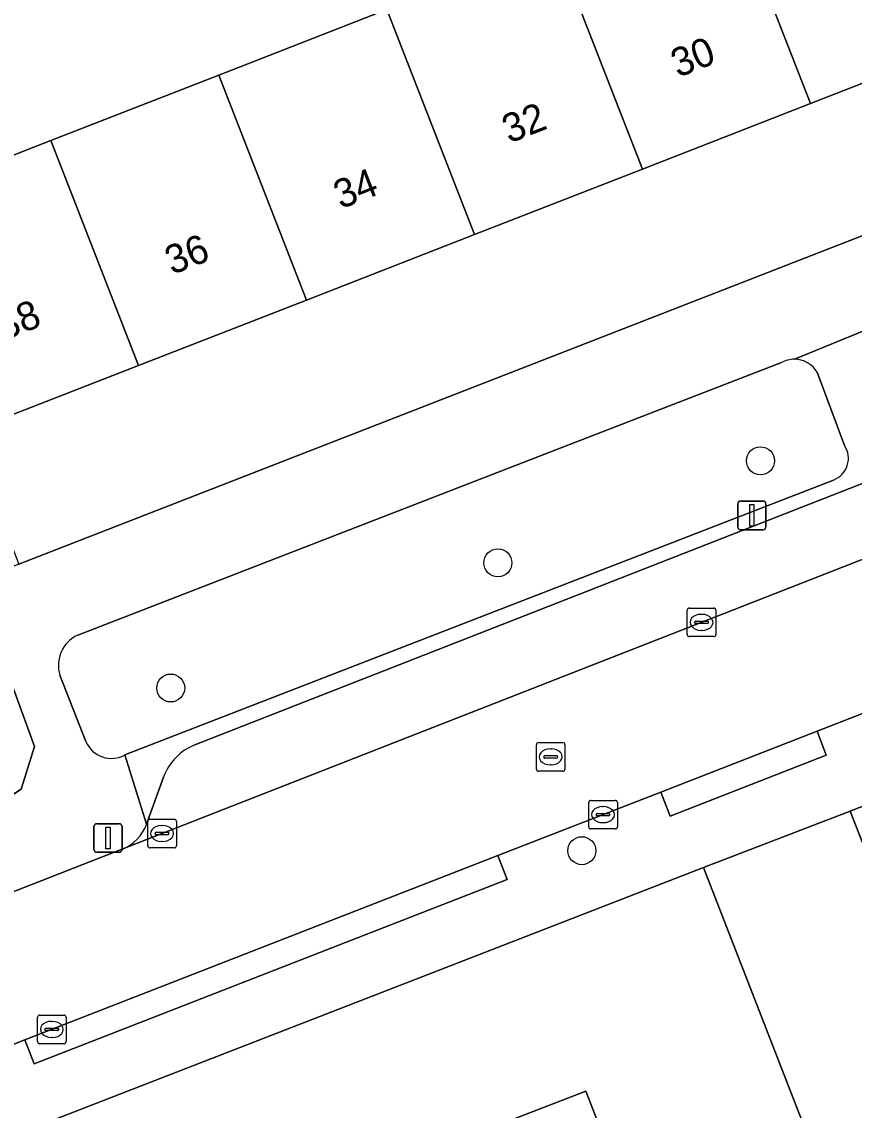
# Model space of a CAD drawing. Extents: x 159680 to 160786, y 387323 to 388340.
# Drawn here: x 160097.77 to 160126.86, y 387603.88 to 387641.92 of the extents above; entities that cross this region are included whole.
import ezdxf

# ---------------------------------------------------------------- set-up
doc = ezdxf.new("R2010")
doc.units = 0
for name, color, linetype in [('IMGEO_Boom', 7, 'Continuous'), ('IMGEO_Erf', 7, 'Continuous'), ('IMGEO_Groenvoorziening', 7, 'Continuous'), ('IMGEO_Kolk', 7, 'Continuous'), ('IMGEO_Lichtmast', 7, 'Continuous'), ('IMGEO_Pand', 7, 'Continuous'), ('IMGEO_Pand_nummerreeks', 7, 'Continuous'), ('IMGEO_Parkeervlak_open', 7, 'Continuous'), ('IMGEO_Rijbaan_lokaal_open', 7, 'Continuous'), ('IMGEO_Rioolput', 7, 'Continuous'), ('IMGEO_Voetpad_open', 7, 'Continuous')]:
    doc.layers.add(name, color=color, linetype=linetype)

msp = doc.modelspace()

# ---------------------------------------------------------------- linework, layer by layer
at = {"layer": 'IMGEO_Boom'}
for centre in [(160123.584, 387626.574), (160114.406, 387623.008), (160102.972, 387618.633), (160117.341, 387612.947)]:
    msp.add_circle(centre, 0.489, dxfattribs=at)
at = {"layer": 'IMGEO_Erf'}
msp.add_lwpolyline([(160156.598, 387645.925), (160154.796, 387650.549), (160148.808, 387648.214), (160142.938, 387645.925), (160137.069, 387643.637), (160131.199, 387641.348), (160125.33, 387639.06), (160119.46, 387636.771), (160113.59, 387634.482), (160107.721, 387632.194), (160101.851, 387629.905), (160095.863, 387627.57), (160097.659, 387622.96)], close=True, dxfattribs=at)
for points in [[(160096.795, 387614.48), (160097.748, 387615.099), (160098.214, 387616.592), (160096.098, 387622.352), (160095.464, 387624.079), (160091.871, 387622.677), (160094.15, 387616.835), (160088.444, 387614.609), (160087.085, 387618.092), (160082.584, 387616.336), (160083.946, 387612.845), (160077.443, 387610.308), (160075.093, 387616.33), (160072.807, 387622.189), (160070.522, 387628.048), (160068.236, 387633.907), (160065.95, 387639.766), (160063.664, 387645.625)], [(160089.993, 387642.31), (160092.798, 387635.431), (160098.785, 387637.766), (160104.655, 387640.055), (160110.525, 387642.343)]]:
    msp.add_lwpolyline(points, dxfattribs=at)
at = {"layer": 'IMGEO_Groenvoorziening'}
for points in [[(160124.322, 387630.011), (160116.432, 387626.958), (160099.72, 387620.484)], [(160126.526, 387627.113), (160125.571, 387629.667)], [(160101.374, 387616.302), (160126.134, 387625.901)], [(160099.099, 387619.08), (160100.009, 387616.763)]]:
    msp.add_lwpolyline(points, dxfattribs=at)
for centre, radius, start, end in [((160124.768, 387629.177), 0.946, 89.8447, 118.1677), ((160124.766, 387629.184), 0.939, 30.9492, 89.6846), ((160125.839, 387626.666), 0.82, 291.1057, 33.0486), ((160100.212, 387619.427), 1.166, 114.968, 197.3116), ((160100.893, 387617.128), 0.956, 202.4282, 300.2492)]:
    msp.add_arc(centre, radius, start, end, dxfattribs=at)
at = {"layer": 'IMGEO_Kolk'}
for p, q in [((160121.099, 387621.428), (160121.951, 387621.428)), ((160121.024, 387620.502), (160121.024, 387621.354)), ((160121.512, 387621.208), (160121.537, 387621.208)), ((160122.025, 387621.354), (160122.025, 387620.502)), ((160121.283, 387620.922), (160121.283, 387620.934)), ((160121.721, 387620.885), (160121.323, 387620.885)), ((160121.326, 387620.971), (160121.724, 387620.971)), ((160121.535, 387620.648), (160121.51, 387620.648)), ((160121.767, 387620.934), (160121.767, 387620.922)), ((160121.951, 387620.428), (160121.099, 387620.428)), ((160117.581, 387613.78), (160117.581, 387614.632)), ((160117.656, 387614.706), (160118.508, 387614.706)), ((160118.582, 387614.632), (160118.582, 387613.78)), ((160117.84, 387614.2), (160117.84, 387614.212)), ((160118.278, 387614.163), (160117.88, 387614.163)), ((160117.883, 387614.249), (160118.281, 387614.249)), ((160118.069, 387614.486), (160118.094, 387614.486)), ((160118.324, 387614.212), (160118.324, 387614.2)), ((160102.168, 387613.12), (160102.168, 387613.972)), ((160102.243, 387614.046), (160103.095, 387614.046)), ((160102.656, 387613.826), (160102.681, 387613.826)), ((160103.169, 387613.972), (160103.169, 387613.12)), ((160118.092, 387613.926), (160118.067, 387613.926)), ((160102.427, 387613.54), (160102.427, 387613.552)), ((160102.865, 387613.503), (160102.467, 387613.503)), ((160102.47, 387613.589), (160102.868, 387613.589)), ((160102.911, 387613.552), (160102.911, 387613.54)), ((160118.508, 387613.706), (160117.656, 387613.706)), ((160103.095, 387613.046), (160102.243, 387613.046)), ((160102.679, 387613.266), (160102.654, 387613.266)), ((160098.316, 387606.275), (160098.316, 387607.127)), ((160098.391, 387607.201), (160099.243, 387607.201)), ((160098.804, 387606.981), (160098.829, 387606.981)), ((160099.317, 387607.127), (160099.317, 387606.275)), ((160098.575, 387606.695), (160098.575, 387606.707)), ((160099.013, 387606.658), (160098.615, 387606.658)), ((160098.618, 387606.744), (160099.016, 387606.744)), ((160099.059, 387606.707), (160099.059, 387606.695)), ((160099.243, 387606.201), (160098.391, 387606.201)), ((160098.827, 387606.421), (160098.802, 387606.421))]:
    msp.add_line(p, q, dxfattribs=at)
for points in [[(160121.099, 387621.428), (160121.951, 387621.428)], [(160121.024, 387620.502), (160121.024, 387621.354)], [(160122.025, 387621.354), (160122.025, 387620.502)], [(160121.951, 387620.428), (160121.099, 387620.428)], [(160117.581, 387613.78), (160117.581, 387614.632)], [(160117.656, 387614.706), (160118.508, 387614.706)], [(160118.582, 387614.632), (160118.582, 387613.78)], [(160102.168, 387613.12), (160102.168, 387613.972)], [(160102.243, 387614.046), (160103.095, 387614.046)], [(160103.169, 387613.972), (160103.169, 387613.12)], [(160118.508, 387613.706), (160117.656, 387613.706)], [(160103.095, 387613.046), (160102.243, 387613.046)], [(160098.316, 387606.275), (160098.316, 387607.127)], [(160098.391, 387607.201), (160099.243, 387607.201)], [(160099.317, 387607.127), (160099.317, 387606.275)], [(160099.243, 387606.201), (160098.391, 387606.201)]]:
    msp.add_lwpolyline(points, dxfattribs=at)
for centre, radius, start, end in [((160121.101, 387621.352), 0.0765, 91.552, 178.448), ((160121.101, 387621.352), 0.0765, 91.552, 178.448), ((160121.949, 387621.352), 0.0765, 1.552, 88.448), ((160121.949, 387621.352), 0.0765, 1.552, 88.448), ((160121.323, 387620.931), 0.0403, 85.8775, 175.7526), ((160121.32, 387620.921), 0.0366, 178.938, 274.7102), ((160121.724, 387620.928), 0.043, 264.8664, 352.4533), ((160121.728, 387620.933), 0.0386, 1.7309, 96.639), ((160121.101, 387620.504), 0.0765, 181.552, 268.448), ((160121.101, 387620.504), 0.0765, 181.552, 268.448), ((160121.949, 387620.504), 0.0765, 271.552, 358.448), ((160121.949, 387620.504), 0.0765, 271.552, 358.448), ((160117.658, 387614.63), 0.0765, 91.552, 178.448), ((160117.658, 387614.63), 0.0765, 91.552, 178.448), ((160118.506, 387614.63), 0.0765, 1.552, 88.448), ((160118.506, 387614.63), 0.0765, 1.552, 88.448), ((160117.88, 387614.209), 0.0403, 85.8775, 175.7526), ((160117.877, 387614.199), 0.0366, 178.938, 274.7102), ((160118.281, 387614.206), 0.043, 264.8664, 352.4533), ((160118.285, 387614.211), 0.0386, 1.7309, 96.639), ((160102.245, 387613.97), 0.0765, 91.552, 178.448), ((160102.245, 387613.97), 0.0765, 91.552, 178.448), ((160103.093, 387613.97), 0.0765, 1.552, 88.448), ((160103.093, 387613.97), 0.0765, 1.552, 88.448), ((160117.658, 387613.782), 0.0765, 181.552, 268.448), ((160117.658, 387613.782), 0.0765, 181.552, 268.448), ((160118.506, 387613.782), 0.0765, 271.552, 358.448), ((160118.506, 387613.782), 0.0765, 271.552, 358.448), ((160102.467, 387613.549), 0.0403, 85.8775, 175.7526), ((160102.464, 387613.539), 0.0366, 178.938, 274.7102), ((160102.868, 387613.546), 0.043, 264.8664, 352.4533), ((160102.872, 387613.551), 0.0386, 1.7309, 96.639), ((160102.245, 387613.122), 0.0765, 181.552, 268.448), ((160102.245, 387613.122), 0.0765, 181.552, 268.448), ((160103.093, 387613.122), 0.0765, 271.552, 358.448), ((160103.093, 387613.122), 0.0765, 271.552, 358.448), ((160098.393, 387607.125), 0.0765, 91.552, 178.448), ((160098.393, 387607.125), 0.0765, 91.552, 178.448), ((160099.241, 387607.125), 0.0765, 1.552, 88.448), ((160099.241, 387607.125), 0.0765, 1.552, 88.448), ((160098.615, 387606.704), 0.0403, 85.8775, 175.7526), ((160098.612, 387606.694), 0.0366, 178.938, 274.7102), ((160099.016, 387606.701), 0.043, 264.8664, 352.4533), ((160099.02, 387606.706), 0.0386, 1.7309, 96.639), ((160098.393, 387606.277), 0.0765, 181.552, 268.448), ((160098.393, 387606.277), 0.0765, 181.552, 268.448), ((160099.241, 387606.277), 0.0765, 271.552, 358.448), ((160099.241, 387606.277), 0.0765, 271.552, 358.448)]:
    msp.add_arc(centre, radius, start, end, dxfattribs=at)
for centre, major_axis, ratio, start_param, end_param in [((160121.511, 387620.928), (-0.387, 0.002), 0.722429, 4.712389, 7.853982), ((160121.536, 387620.928), (-0.39, 0.002), 0.717154, 1.570796, 4.712389), ((160118.068, 387614.206), (-0.387, 0.002), 0.722429, 4.712389, 7.853982), ((160118.093, 387614.206), (-0.39, 0.002), 0.717154, 1.570796, 4.712389), ((160102.655, 387613.546), (-0.387, 0.002), 0.722429, 4.712389, 7.853982), ((160102.68, 387613.546), (-0.39, 0.002), 0.717154, 1.570796, 4.712389), ((160098.803, 387606.701), (-0.387, 0.002), 0.722429, 4.712389, 7.853982), ((160098.828, 387606.701), (-0.39, 0.002), 0.717154, 1.570796, 4.712389)]:
    msp.add_ellipse(centre, major_axis=major_axis, ratio=ratio, start_param=start_param, end_param=end_param, dxfattribs=at)
at = {"layer": 'IMGEO_Lichtmast'}
for p, q in [((160122.788, 387624.267), (160122.788, 387625.067)), ((160122.788, 387625.067), (160122.788, 387624.267)), ((160122.888, 387625.167), (160123.678, 387625.167)), ((160123.678, 387625.167), (160122.888, 387625.167)), ((160123.778, 387625.067), (160123.778, 387624.267)), ((160123.778, 387624.267), (160123.778, 387625.067)), ((160123.678, 387624.167), (160122.888, 387624.167)), ((160122.888, 387624.167), (160123.678, 387624.167)), ((160100.285, 387612.991), (160100.285, 387613.791)), ((160100.285, 387613.791), (160100.285, 387612.991)), ((160100.385, 387613.891), (160101.175, 387613.891)), ((160101.175, 387613.891), (160100.385, 387613.891)), ((160101.275, 387613.791), (160101.275, 387612.991)), ((160101.275, 387612.991), (160101.275, 387613.791)), ((160101.175, 387612.891), (160100.385, 387612.891)), ((160100.385, 387612.891), (160101.175, 387612.891))]:
    msp.add_line(p, q, dxfattribs=at)
for points in [[(160123.208, 387625.042), (160123.358, 387625.042), (160123.358, 387624.292), (160123.208, 387624.292), (160123.208, 387625.042)], [(160100.705, 387613.766), (160100.855, 387613.766), (160100.855, 387613.016), (160100.705, 387613.016), (160100.705, 387613.766)]]:
    msp.add_lwpolyline(points, dxfattribs=at)
for centre, start, end in [((160122.888, 387625.067), 90, 180), ((160122.888, 387625.067), 90, 180), ((160123.678, 387625.067), 0, 90), ((160123.678, 387625.067), 360, 90), ((160122.888, 387624.267), 180, 270), ((160122.888, 387624.267), 180, 270), ((160123.678, 387624.267), 270, 0), ((160123.678, 387624.267), 270, 0), ((160100.385, 387613.791), 90, 180), ((160100.385, 387613.791), 90, 180), ((160101.175, 387613.791), 0, 90), ((160101.175, 387613.791), 360, 90), ((160100.385, 387612.991), 180, 270), ((160100.385, 387612.991), 180, 270), ((160101.175, 387612.991), 270, 0), ((160101.175, 387612.991), 270, 0)]:
    msp.add_arc(centre, 0.1, start, end, dxfattribs=at)
at = {"layer": 'IMGEO_Pand'}
for points in [[(160122.265, 387646.921), (160122.024, 387646.827), (160120.823, 387649.907), (160115.194, 387647.712), (160116.395, 387644.632), (160119.46, 387636.771), (160125.33, 387639.06)], [(160128.133, 387649.209), (160122.265, 387646.921), (160125.33, 387639.06), (160131.199, 387641.348)], [(160116.395, 387644.632), (160110.525, 387642.343), (160113.59, 387634.482), (160119.46, 387636.771)], [(160110.525, 387642.343), (160104.655, 387640.055), (160107.721, 387632.194), (160113.59, 387634.482)], [(160101.851, 387629.905), (160107.721, 387632.194), (160104.655, 387640.055), (160098.785, 387637.766)], [(160098.785, 387637.766), (160092.798, 387635.431), (160094.047, 387632.229), (160095.863, 387627.57), (160101.851, 387629.905)], [(160117.476, 387604.545), (160114.677, 387603.454), (160116.914, 387597.714), (160119.694, 387598.853)]]:
    msp.add_lwpolyline(points, close=True, dxfattribs=at)
at = {"layer": 'IMGEO_Parkeervlak_open'}
for points in [[(160210.973, 387658.364), (160203.991, 387655.625), (160155.591, 387636.914), (160103.815, 387616.643)], [(160101.294, 387613.006), (160156.486, 387634.615), (160204.886, 387653.326), (160214.931, 387657.325)], [(160102.719, 387615.515), (160102.13, 387613.868)]]:
    msp.add_lwpolyline(points, dxfattribs=at)
for points in [[(160132.833, 387616.731), (160126.718, 387614.332), (160131.091, 387603.167), (160132.433, 387603.683), (160136.118, 387605.099), (160137.223, 387605.524)], [(160096.623, 387596.353), (160099.423, 387597.447), (160099.666, 387597.554), (160100.682, 387598.002), (160103.481, 387599.093), (160106.28, 387600.183), (160109.079, 387601.273), (160111.878, 387602.364), (160114.677, 387603.454), (160117.476, 387604.545), (160119.694, 387598.853), (160120.666, 387599.232), (160124.494, 387600.62), (160125.952, 387601.148), (160121.589, 387612.364), (160094.971, 387602.03), (160080.6, 387596.491), (160082.745, 387590.933), (160085.423, 387591.979), (160088.223, 387593.072), (160091.023, 387594.166), (160093.823, 387595.26)]]:
    msp.add_lwpolyline(points, close=True, dxfattribs=at)
for centre, radius, start, end in [((160104.507, 387614.874), 1.899, 111.3682, 160.2805), ((160100.672, 387614.445), 1.568, 293.3604, 338.3941)]:
    msp.add_arc(centre, radius, start, end, dxfattribs=at)
at = {"layer": 'IMGEO_Rijbaan_lokaal_open'}
for points in [[(160186.627, 387640.98), (160190.898, 387642.649), (160191.872, 387643.028), (160198.813, 387645.729), (160215.815, 387652.344), (160216.969, 387652.793), (160234.315, 387659.622), (160234.917, 387659.859), (160239.576, 387661.665), (160239.911, 387661.795), (160240.137, 387661.885), (160238.288, 387666.596), (160237.289, 387666.167), (160234.152, 387664.978), (160219.832, 387659.26), (160215.649, 387657.619), (160215.343, 387657.428), (160215.107, 387657.369), (160214.931, 387657.325), (160204.886, 387653.326), (160156.486, 387634.615), (160101.294, 387613.006), (160079.639, 387604.528)], [(160077.784, 387598.503), (160079.135, 387599.03), (160096.713, 387605.88), (160097.873, 387606.332), (160114.407, 387612.775), (160120.1, 387614.994), (160125.563, 387617.123), (160134.686, 387620.678), (160186.627, 387640.98)], [(160132.433, 387603.683), (160131.091, 387603.167), (160126.718, 387614.332), (160121.589, 387612.364), (160125.952, 387601.148), (160124.494, 387600.62)]]:
    msp.add_lwpolyline(points, dxfattribs=at)
at = {"layer": 'IMGEO_Rioolput'}
for p, q in [((160115.751, 387615.8), (160115.751, 387616.652)), ((160115.826, 387616.726), (160116.678, 387616.726)), ((160116.239, 387616.506), (160116.264, 387616.506)), ((160116.752, 387616.652), (160116.752, 387615.8)), ((160116.01, 387616.22), (160116.01, 387616.232)), ((160116.448, 387616.183), (160116.05, 387616.183)), ((160116.053, 387616.269), (160116.451, 387616.269)), ((160116.494, 387616.232), (160116.494, 387616.22)), ((160116.678, 387615.726), (160115.826, 387615.726)), ((160116.262, 387615.946), (160116.237, 387615.946))]:
    msp.add_line(p, q, dxfattribs=at)
for points in [[(160115.751, 387615.8), (160115.751, 387616.652)], [(160115.826, 387616.726), (160116.678, 387616.726)], [(160116.752, 387616.652), (160116.752, 387615.8)], [(160116.678, 387615.726), (160115.826, 387615.726)]]:
    msp.add_lwpolyline(points, dxfattribs=at)
for centre, radius, start, end in [((160115.828, 387616.65), 0.0765, 91.552, 178.448), ((160115.828, 387616.65), 0.0765, 91.552, 178.448), ((160116.676, 387616.65), 0.0765, 1.552, 88.448), ((160116.676, 387616.65), 0.0765, 1.552, 88.448), ((160116.05, 387616.229), 0.0403, 85.8775, 175.7526), ((160116.047, 387616.219), 0.0366, 178.938, 274.7102), ((160116.451, 387616.226), 0.043, 264.8664, 352.4533), ((160116.455, 387616.231), 0.0386, 1.7309, 96.639), ((160115.828, 387615.802), 0.0765, 181.552, 268.448), ((160115.828, 387615.802), 0.0765, 181.552, 268.448), ((160116.676, 387615.802), 0.0765, 271.552, 358.448), ((160116.676, 387615.802), 0.0765, 271.552, 358.448)]:
    msp.add_arc(centre, radius, start, end, dxfattribs=at)
for centre, major_axis, ratio, start_param, end_param in [((160116.238, 387616.226), (-0.387, 0.002), 0.722429, 4.712389, 7.853982), ((160116.263, 387616.226), (-0.39, 0.002), 0.717154, 1.570796, 4.712389)]:
    msp.add_ellipse(centre, major_axis=major_axis, ratio=ratio, start_param=start_param, end_param=end_param, dxfattribs=at)
at = {"layer": 'IMGEO_Voetpad_open'}
for points in [[(160212.494, 387667.704), (160211.11, 387667.165), (160158.078, 387646.502), (160156.598, 387645.925), (160097.659, 387622.96), (160096.098, 387622.352), (160098.214, 387616.592), (160097.748, 387615.099), (160096.795, 387614.48), (160077.652, 387606.937), (160079.639, 387604.528), (160101.294, 387613.006)], [(160103.815, 387616.643), (160155.591, 387636.914), (160203.991, 387655.625), (160210.973, 387658.364)], [(160216.141, 387651.505), (160199.139, 387644.89), (160198.813, 387645.729), (160191.872, 387643.028), (160192.199, 387642.19), (160186.954, 387640.142), (160186.627, 387640.98), (160134.686, 387620.678), (160125.563, 387617.123), (160125.886, 387616.283), (160120.423, 387614.154), (160120.1, 387614.994), (160114.407, 387612.775), (160114.73, 387611.935), (160098.196, 387605.492), (160097.873, 387606.332), (160096.713, 387605.88), (160097.036, 387605.04), (160079.892, 387598.359), (160079.458, 387598.19), (160079.135, 387599.03), (160077.784, 387598.503)], [(160079.567, 387589.77), (160082.623, 387590.885), (160082.745, 387590.933), (160080.6, 387596.491), (160094.971, 387602.03), (160121.589, 387612.364), (160126.718, 387614.332), (160132.833, 387616.731), (160133.717, 387617.078), (160180.916, 387635.628)], [(160127.276, 387631.147), (160124.771, 387630.123)], [(160124.771, 387630.123), (160127.276, 387631.147)], [(160099.72, 387620.484), (160116.432, 387626.958), (160124.322, 387630.011)], [(160125.571, 387629.667), (160126.526, 387627.113)], [(160126.134, 387625.901), (160101.374, 387616.302), (160102.13, 387613.868), (160102.719, 387615.515)], [(160100.009, 387616.763), (160099.099, 387619.08)], [(160102.13, 387613.868), (160101.374, 387616.302)]]:
    msp.add_lwpolyline(points, dxfattribs=at)
for points in [[(160125.563, 387617.123), (160120.1, 387614.994), (160120.423, 387614.154), (160125.886, 387616.283)], [(160114.407, 387612.775), (160097.873, 387606.332), (160098.196, 387605.492), (160114.73, 387611.935)]]:
    msp.add_lwpolyline(points, close=True, dxfattribs=at)
for centre, radius, start, end in [((160124.768, 387629.177), 0.946, 89.8447, 118.1677), ((160124.766, 387629.184), 0.939, 30.9492, 89.6846), ((160125.839, 387626.666), 0.82, 291.1057, 33.0486), ((160100.212, 387619.427), 1.166, 114.968, 197.3116), ((160100.893, 387617.128), 0.956, 202.4282, 300.2492), ((160104.507, 387614.874), 1.899, 111.3682, 160.2805), ((160100.672, 387614.445), 1.568, 293.3604, 338.3941)]:
    msp.add_arc(centre, radius, start, end, dxfattribs=at)

# ---------------------------------------------------------------- texts
at = {"layer": 'IMGEO_Pand_nummerreeks'}
for s, rotation, p in [('30', 21.3026, (160120.7, 387639.958)), ('32', 21.3017, (160114.802, 387637.66)), ('34', 21.3017, (160108.911, 387635.363)), ('36', 21.3017, (160103.017, 387633.065)), ('38', 21.3017, (160097.127, 387630.768))]:
    msp.add_text(s, height=1, rotation=rotation, dxfattribs=at).set_placement(p)

doc.saveas('drawing.dxf')
